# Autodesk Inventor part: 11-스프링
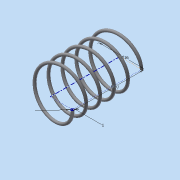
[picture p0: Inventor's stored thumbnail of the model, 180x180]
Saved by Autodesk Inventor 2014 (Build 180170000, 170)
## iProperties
Created: 2015-06
Part Number: 11-스프링
Material: 강철, 연강
Document SubType Name: Modeling
Designer: MYHOME
Density: 1 g/cm^3
Appearance: 강철
Author: MYHOME
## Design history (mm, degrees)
sketch "스케치1"
  geometry: L1 (0, 0)-(8, 0); L2 (8, 0)-(8, 21.5); L3 (8, 21.5)-(0, 21.5); L4 (0, 21.5)-(0, 0); C1 r 0.5 at (8, 0)
  constraints: 8 end point, 2 parallel, 1 centre point, 1 coincident, 1 horizontal, 1 perpendicular
  dimensions: "d0" = 1 diameter of C1; "d1" = 16 diameter of L2 L4; "d2" = 21.5 distance of L1.end L2.end (derived)
feature "코일1" sketch "스케치1" pitch "d3" = 10; turns "d5" = 5; dims "d4" = 21.5 (= d2), "d6" = 0, angle "d7" = 90 deg, angle "d8" = 90 deg, "d9" = 0, "d10" = 0
sketch "스케치2"
  geometry: L1 (-8.5, 0)-(-7.5, 0) reference; 1 further point
  constraints: 1 horizontal alignment
extrude "돌출1" cut sketch "스케치2" stored distance "d11" = 10; taper "d12" = 0 deg
node "작업 평면1"
sketch "스케치3"
  geometry: L1 (-7.5, 0)-(-8.5, 0) reference; 1 further point
  constraints: 1 horizontal alignment
extrude "돌출2" cut sketch "스케치3" stored distance "d14" = 10; taper "d15" = 0 deg
node "솔리드1"
node "절단 모서리 투영1"
node "절단 모서리 투영2"
other parameters: "d13" = 21.5 (= d2)
